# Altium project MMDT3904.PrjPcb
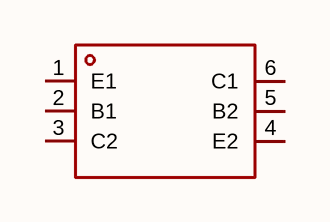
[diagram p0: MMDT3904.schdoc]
1 sheet, 1 parts. Net scope: global (net labels, ports and power ports of the same name join across sheets).

## Sheet MMDT3904.schdoc
size 127 x 101 mm

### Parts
Q?  mmdt3904_c21664  [SOT-363_L2.0-W1.3-P0.65-LS2.1-BR]  (value not drawn)

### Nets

Not connected (* = marked no-connect by the designer): Q? 1(E1) 2(B1) 3(C2) 4(E2) 5(B2) 6(C1)

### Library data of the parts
Q? = mmdt3904_c21664: 晶体管类型:NPN;集电极电流(Ic):200mA;集射极击穿电压(Vceo):40V;耗散功率(Pd):200mW;直流电流增益(hFE):40;; Manufacturer: CJ(江苏长电/长晶); AddInBom: yes; ModelId: ea15c7b026c54341854a7f0d9614aed9; ModelName: SOT-363-6P_L2.0-W1.3-H1.1-LS2.0-P0.65; ModelTransform: 78.74,82.677,0,90,0,0,0,0,0; type: NPN; Current - Collector(Ic): 200mA; Collector - Emitter Voltage VCEO: 40V; Pd - Power Dissipation: 200mW; DC Current Gain: 40; Transition frequency(fT): 300MHz; Current - Collector Cutoff: 50nA; Vce Saturation(VCE(sat)): 300mV; Emitter-Base Voltage(Vebo): 5V; Number: 2个NPN; Configuration: 独立式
